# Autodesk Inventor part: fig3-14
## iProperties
Created: 2005-02
Part Number: fig3-14
Document SubType Name: Modeling
Designer: CADCIM
Manufacturer: Standard
Standards Organization: Custom
Author: CADCIM
